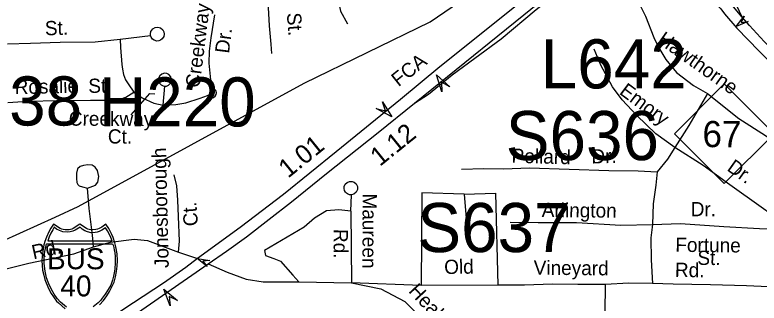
# Model space of a CAD drawing. Extents: x 1547597 to 1699558, y 810033 to 920809.
# Drawn here: x 1609660 to 1614635, y 849388 to 851314 of the extents above; entities that cross this region are included whole.
import ezdxf

# ---------------------------------------------------------------- set-up
doc = ezdxf.new("R2010")
doc.units = 0
for name, color, linetype in [('Exist Hydrographic Creek Single Shore', 7, 'Continuous'), ('Exist Road Non-System Type 51', 7, 'Continuous'), ('Exist Road Non-System Type 51 Label', 7, 'Continuous'), ('Exist Road Primary Interstate Divided Center Attributed', 7, 'Continuous'), ('Exist Road Primary Interstate Label', 7, 'Continuous'), ('Exist Road Primary Interstate Mileage Hundredths English Label', 7, 'Continuous'), ('Exist Road Primary Interstate Ramp 1 Lane Attributed', 7, 'Continuous'), ('Exist Road Primary Interstate Shield CELL', 7, 'Continuous'), ('Exist Road Primary Interstate Shield Number Label', 7, 'Continuous'), ('Exist Road Primary Interstate Structure Cantilever Sign Attributed CELL', 7, 'Continuous'), ('Exist Road Primary Interstate Structure Cantilever Sign Number Label', 7, 'Continuous'), ('Exist Road Primary Interstate Structure Ovrhead Sign Attributed CELL', 7, 'Continuous'), ('Exist Road Primary Interstate Structure Ovrhead Sign Number Label', 7, 'Continuous'), ('Exist Road Primary NC Divided Attributed', 7, 'Continuous'), ('Exist Road Primary NC Shield CELL', 7, 'Continuous'), ('Exist Road Primary NC Shield Number Label', 7, 'Continuous'), ('Exist Road Primary US Structure Non-Sys NCDOT Attributed CELL', 7, 'Continuous'), ('Exist Road Primary US Structure Non-Sys NCDOT Number Label', 7, 'Continuous')]:
    doc.layers.add(name, color=color, linetype=linetype)

msp = doc.modelspace()

# ---------------------------------------------------------------- linework, layer by layer
at = {"layer": 'Exist Hydrographic Creek Single Shore'}
for points in [[(1611594.1, 850857.9), (1612435.7, 851267.3), (1612822.7, 851531.9), (1613218.5, 851977.1), (1613319.3, 852016.9), (1613622.3, 852090.4), (1613757.8, 852160.1), (1613932.3, 852362.2), (1614064.9, 852556.6), (1614161.3, 852672.3), (1614372.7, 852674), (1614458.3, 852674), (1614584.2, 852789.9), (1615148.9, 852985.6), (1615306.6, 853204), (1615898.7, 853406.3), (1616283.8, 853510.1), (1617321.6, 853814.1), (1617885.8, 853975.5), (1618594.7, 854297), (1618697.7, 854345.4)], [(1609928.9, 849962.7), (1610082, 850033.2), (1611594.1, 850857.9)], [(1608890.7, 849280.9), (1609034.9, 849494.6), (1609101.1, 849537.2), (1609268.7, 849655.2), (1609454.2, 849749.5), (1609928.9, 849962.7)]]:
    msp.add_lwpolyline(points, dxfattribs=at)
at = {"layer": 'Exist Road Non-System Type 51'}
for p, q in [((1610363, 851151.8), (1610567.2, 851176.1)), ((1610650.6, 850710.7), (1610662.8, 850838.5))]:
    msp.add_line(p, q, dxfattribs=at)
for points in [[(1611803.9, 851681), (1611807.5, 851554.7), (1611811.1, 851457.3), (1611836.4, 851338.2), (1611883.2, 851255.3)], [(1611349.6, 851673.8), (1611342.3, 851536.7), (1611353.2, 851363.5), (1611360.4, 851240.8), (1611371.2, 851118.1), (1611374.8, 851056.8)], [(1613824.7, 851408.5), (1613874.8, 851305.7), (1613932.2, 851162.6), (1613964.8, 851094.1), (1614011.1, 851017.3), (1614083.7, 850930.2), (1614196.1, 850843.1), (1614289.6, 850789.6)], [(1610970.3, 850824.9), (1610969.5, 850880.7), (1610959.5, 850991), (1610961.3, 851071.4), (1610972.5, 851160.6), (1610995.5, 851314)], [(1610567.2, 851176.1), (1610565.9, 851188.7), (1610569.4, 851204.4), (1610581.9, 851220.4), (1610597.7, 851229.5), (1610614.6, 851231.7), (1610632.7, 851227.2), (1610648.1, 851214.2), (1610655.4, 851200.5), (1610657.9, 851185.4), (1610654.9, 851169.3), (1610645, 851153.7), (1610633.2, 851144.9), (1610622.1, 851140.5), (1610607.7, 851139.6), (1610591.2, 851144.4), (1610579.4, 851152.8), (1610570.6, 851165.4), (1610567.2, 851176.1)], [(1609611.2, 851121.6), (1609765.2, 851124.9), (1609963, 851131.3), (1610197, 851134.9), (1610363, 851151.8)], [(1610363, 851151.8), (1610366.1, 851095.7), (1610374.8, 850982.8), (1610378.8, 850950.7), (1610386.7, 850915.6), (1610399.8, 850881.1), (1610417.4, 850852.9), (1610454.3, 850798.3)], [(1614072.1, 850427.3), (1613944.1, 850519.2), (1613817.9, 850641.9), (1613720.5, 850746.5), (1613655.6, 850833.1), (1613576.3, 850977.4), (1613533, 851085.7)], [(1610662.8, 850838.5), (1610672.3, 850838.9), (1610687.2, 850844.6), (1610702.1, 850860.1), (1610707.1, 850880.7), (1610702.5, 850901.4), (1610689, 850916.4), (1610675.6, 850922.9), (1610660, 850924.8), (1610642.1, 850919), (1610629.4, 850907.4), (1610620.9, 850892.4), (1610620.5, 850874), (1610626.4, 850858.3), (1610638.6, 850846), (1610651.3, 850839.8), (1610662.8, 850838.5)], [(1609612.1, 850729.8), (1609746.1, 850737.5), (1609949.9, 850741.7), (1610165.7, 850743.8), (1610311.6, 850745), (1610364.1, 850751.7), (1610401.8, 850765.4), (1610454.3, 850798.3)], [(1610436.2, 850647.3), (1610561, 850789.4), (1610595.4, 850787.2)], [(1610454.3, 850798.3), (1610511.6, 850759.3), (1610588.9, 850724), (1610650.6, 850710.7)], [(1610947.5, 850775.3), (1610955.5, 850766.3), (1610965.4, 850761.5), (1610977.2, 850760.1), (1610988.3, 850762.7), (1610999, 850770.9), (1611005.7, 850782.1), (1611007.9, 850794.5), (1611003, 850809.2), (1610992.4, 850820.2), (1610979.9, 850825.1), (1610970.3, 850824.9)], [(1610947.5, 850775.3), (1610971.2, 850789.6), (1610970.3, 850824.9)], [(1614289.6, 850789.6), (1614213.4, 850655.3), (1614166.4, 850576.1), (1614072.1, 850427.3)], [(1614289.6, 850789.6), (1614499.9, 850622.6), (1614679.1, 850508.9), (1614923.7, 850344.4), (1615083.8, 850219.7)], [(1610650.6, 850710.7), (1610736.6, 850715.2), (1610802.6, 850726), (1610899.1, 850758.1), (1610947.5, 850775.3)], [(1614072.1, 850427.3), (1614022.9, 850349.3), (1613953.4, 850264.5)], [(1614855.5, 849882.8), (1614648.3, 850030.5), (1614439.2, 850178.2), (1614260.7, 850307.5), (1614072.1, 850427.3)], [(1610144.7, 850155.6), (1610199.2, 850177.4), (1610213.6, 850197.1), (1610220.2, 850235), (1610213, 850275.1), (1610197.4, 850297.3), (1610175.7, 850309.7), (1610147.7, 850312.3), (1610117.6, 850308.7), (1610095.6, 850301.1), (1610079.3, 850285.4), (1610070.7, 850255.6), (1610072.2, 850221.8), (1610074.1, 850194.3), (1610080.6, 850180), (1610089.6, 850171.4), (1610111.1, 850164.9), (1610144.7, 850155.6)], [(1612645.3, 850284.4), (1612795.2, 850287.6), (1612926.8, 850285.3), (1613100.8, 850293.2), (1613365.5, 850282.3), (1613630, 850274.4), (1613827.7, 850272.8), (1613953.4, 850264.5)], [(1610754.6, 849727.8), (1610760.1, 849803.4), (1610754.6, 849967.5), (1610749.1, 850076.3), (1610741.8, 850171.8), (1610723.9, 850244.9)], [(1613953.4, 850264.5), (1613945.8, 850176.8), (1613927.4, 850051.1), (1613923, 849913.3)], [(1611883.6, 850117.8), (1611876.2, 850122.3), (1611869.2, 850130.3), (1611863.6, 850140.6), (1611860.3, 850154.1), (1611861.4, 850168.4), (1611867.4, 850182.1), (1611881.1, 850195.3), (1611895.9, 850201.6), (1611914.1, 850201.6), (1611928.4, 850196.1), (1611940.4, 850185.9), (1611950, 850167.4), (1611949.4, 850146.7), (1611941.8, 850129.2), (1611925.7, 850116.3), (1611910.8, 850111.8), (1611897.7, 850112.9), (1611883.6, 850117.8)], [(1610184.9, 849765.3), (1610177.9, 849842.1), (1610155.7, 850021), (1610144.7, 850155.6)], [(1611904.8, 850003.2), (1611910.8, 850111.8)], [(1612380.1, 850126.2), (1612376.5, 849505.5)], [(1612663, 850115.3), (1612380.1, 850126.2)], [(1612663, 850115.3), (1612873.3, 850122.6)], [(1612663, 850115.3), (1612681.1, 849901.2)], [(1612873.3, 850122.6), (1612888.7, 849508.1)], [(1611904.8, 850003.2), (1611824.5, 850011.3), (1611742.1, 850005.3), (1611663.8, 849957), (1611593.4, 849896.7), (1611328.3, 849739.9)], [(1611904.8, 850003.2), (1611909.7, 849523)], [(1612970.2, 849930.2), (1613157.8, 849926.9), (1613413.5, 849926.1), (1613711, 849909.2), (1613923, 849913.3)], [(1613923, 849913.3), (1613911.4, 849823.5), (1613912.6, 849677.6), (1613921.6, 849519.5)], [(1613923, 849913.3), (1614108.9, 849919.9), (1614398.5, 849901), (1614637.9, 849886.4), (1614855.5, 849882.8)], [(1610184.9, 849765.3), (1610299.7, 849795), (1610457, 849816.3), (1610546.3, 849807.8), (1610754.6, 849727.8)], [(1608516.1, 849735.5), (1608958.3, 849658.9), (1609302.8, 849590.8), (1609528.1, 849599.3), (1609753.5, 849654.7), (1610053.1, 849718.4), (1610184.9, 849765.3)], [(1611328.3, 849739.9), (1611334.3, 849705.7), (1611390.6, 849685.6), (1611434.7, 849669.5), (1611517.1, 849575), (1611558.4, 849531.2)], [(1610754.6, 849727.8), (1610880.9, 849686.6)], [(1610951.8, 849650.5), (1611077.9, 849595), (1611205.5, 849548.2), (1611320.3, 849531.2), (1611558.4, 849531.2)], [(1611558.4, 849531.2), (1611909.7, 849523)], [(1611909.7, 849523), (1612105.3, 849484.7), (1612266.9, 849399.5), (1612424.2, 849242.1), (1612589.7, 849074.1)], [(1612376.5, 849505.5), (1611909.7, 849523)], [(1612888.7, 849508.1), (1612376.5, 849505.5)], [(1613607.9, 849513.1), (1613423.5, 849512.8), (1613253.4, 849514.7), (1613066.1, 849508.1), (1612888.7, 849508.1)], [(1613616.3, 848999.2), (1613606.9, 849135.3), (1613606.3, 849323.2), (1613607.9, 849513.1)], [(1613921.6, 849519.5), (1613761.8, 849522.4), (1613607.9, 849513.1)], [(1615139.8, 849441.5), (1615073.2, 849463.1), (1615051.3, 849474.8), (1614934, 849486.3), (1614796.8, 849491.6), (1614550.7, 849503.9), (1614311.1, 849510.4), (1614061.4, 849514.9), (1613921.6, 849519.5)]]:
    msp.add_lwpolyline(points, dxfattribs=at)
at = {"layer": 'Exist Road Primary Interstate Divided Center Attributed'}
for points in [[(1612330.6, 850725.5), (1613224.7, 851447.9), (1613346.8, 851542.9), (1613591.4, 851734.7), (1613886.3, 851991.7)], [(1613010.2, 851375.8), (1612501.3, 850967.3), (1612238.6, 850748.3), (1611807.5, 850398.9), (1611455.2, 850113.6), (1611165.3, 849893.8), (1610880.9, 849686.6)], [(1609818, 848863.7), (1610951.8, 849650.5), (1611075.2, 849735.8), (1611208.1, 849832), (1611360.5, 849948.2), (1611508.2, 850064.4), (1611742.4, 850253.5), (1612088.1, 850529.5), (1612330.6, 850725.5)], [(1610880.9, 849686.6), (1610801.9, 849625.3), (1610654, 849520.7), (1610451.7, 849389.8), (1610101.9, 849158.9), (1609835, 848982.1), (1609597.4, 848825.8)]]:
    msp.add_lwpolyline(points, dxfattribs=at)
at = {"layer": 'Exist Road Primary Interstate Ramp 1 Lane Attributed'}
for points in [[(1614522.4, 851299.9), (1614466.2, 851418.6), (1614445.7, 851474.8), (1614436.9, 851512), (1614425.3, 851584.9), (1614423, 851653.9), (1614424.4, 851686.9), (1614426.7, 851723.6), (1614431, 851830.6), (1614433.4, 851880.4), (1614440.5, 851930.2), (1614442.8, 851987.1), (1614447.6, 852041.6), (1614457, 852164.8), (1614461.8, 852233.6), (1614473.6, 852290.4), (1614483.1, 852328.4), (1614492.6, 852356.8), (1614511.5, 852387.6), (1614530.5, 852413.7), (1614558.9, 852449.2), (1614594.4, 852484.8), (1614690.2, 852571.5)], [(1612330.6, 850725.5), (1612424.5, 850784.1), (1612582.5, 850913.7), (1612735.8, 851026.2), (1612911.5, 851155.4), (1613143.8, 851351), (1613297.1, 851470.7), (1613360.4, 851491.1), (1613412.5, 851502.3), (1613451.5, 851507.9), (1613498, 851511.6), (1613617.8, 851514.9), (1613713.9, 851519.1), (1613851.6, 851526.5), (1614000.4, 851532.1), (1614091.6, 851530.2), (1614139.9, 851526.5), (1614179, 851515.3), (1614214.4, 851500.4), (1614242.3, 851481.8), (1614272, 851459.5), (1614311.1, 851424.1), (1614379.4, 851353.8)]]:
    msp.add_lwpolyline(points, dxfattribs=at)
at = {"layer": 'Exist Road Primary Interstate Shield CELL'}
for points in [[(1610225.7, 849377.4), (1610251.7, 849404.8), (1610274.7, 849435.9), (1610293, 849464.9), (1610309, 849498), (1610322.5, 849529), (1610333.1, 849564.3), (1610340.2, 849598.5), (1610343.8, 849634.2), (1610346.2, 849673.8), (1610343.5, 849718.3), (1610335.7, 849763.9), (1610328.5, 849792.2), (1610317.4, 849826.2), (1610308.4, 849847.9), (1610287.6, 849886.3), (1610268.8, 849915.9), (1610241.6, 849896.7), (1610223.8, 849887.3), (1610213, 849882.4), (1610201.9, 849880.2), (1610181.4, 849877.8), (1610168.5, 849878.3), (1610156.5, 849881), (1610146.4, 849883.2), (1610138.2, 849887.3), (1610093.9, 849915.9), (1610049.6, 849887.3), (1610040.4, 849883), (1610030.9, 849881), (1610021.7, 849878.5), (1610006.6, 849877.8), (1609995, 849878.1), (1609983.1, 849880.2), (1609973.8, 849882.2), (1609963.2, 849887.3), (1609918.1, 849915.9), (1609900.4, 849890.2), (1609885.9, 849864.8), (1609870.6, 849828.8), (1609861, 849801), (1609854.2, 849778.1), (1609845.9, 849736.2), (1609841.6, 849699.6), (1609840.8, 849673.8), (1609845.5, 849609.3), (1609852.6, 849574.9), (1609859.8, 849547.1), (1609883.7, 849487.1), (1609901.6, 849453.5), (1609917, 849429.3), (1609938.6, 849402.1), (1609950.3, 849389.2), (1609995.1, 849350)], [(1610003.9, 849361.3), (1609964.1, 849393.9), (1609942.7, 849419), (1609922.6, 849448.4), (1609904.8, 849478.5), (1609885.7, 849518.2), (1609872.2, 849558.1), (1609862.4, 849601.1), (1609855.8, 849653.8), (1609855.1, 849685.8), (1609857.1, 849716.7), (1609860, 849732.8), (1609863.9, 849752.9), (1609871.8, 849783.9), (1610313.4, 849784.1), (1610318.1, 849771.9), (1610324.4, 849744.9), (1610327.8, 849724), (1610331.2, 849700), (1610330, 849658.9), (1610328, 849616.3), (1610324.1, 849591.1), (1610318.9, 849568.2), (1610311.7, 849542.7), (1610300.2, 849508.9), (1610284.3, 849480.2), (1610264.4, 849448.4), (1610242.9, 849420.5), (1610233.6, 849409), (1610215.9, 849390.3), (1610183.6, 849364.4)]]:
    msp.add_lwpolyline(points, dxfattribs=at)
msp.add_lwpolyline([(1609923.5, 849895.1), (1609912.5, 849878.2), (1609899.8, 849855.4), (1609889.7, 849831.7), (1609879.3, 849805.5), (1610310.9, 849805.4), (1610300.8, 849827.8), (1610290.1, 849850.3), (1610278.8, 849870.9), (1610265.1, 849890.8), (1610240.9, 849875.6), (1610223.3, 849867.2), (1610209.1, 849862.3), (1610197.1, 849859.6), (1610178.5, 849858.2), (1610170.2, 849858.7), (1610144.3, 849864.5), (1610126.7, 849871.7), (1610110, 849882.9), (1610096.5, 849895.6), (1610062.3, 849874.9), (1610047.2, 849868.2), (1610029.7, 849863.8), (1610010.6, 849861.4), (1609981.2, 849864.6), (1609958.1, 849872.5), (1609938.2, 849882.9)], close=True, dxfattribs=at)
at = {"layer": 'Exist Road Primary Interstate Structure Cantilever Sign Attributed CELL'}
msp.add_lwpolyline([(1610697.9, 849369.4), (1610655.1, 849481), (1610747.9, 849405.8), (1610690.2, 849432.7)], close=True, dxfattribs=at)
at = {"layer": 'Exist Road Primary Interstate Structure Ovrhead Sign Attributed CELL'}
for points in [[(1614562.4, 851269.8), (1614480.9, 851237.1), (1614535.1, 851306.2), (1614516.1, 851263.4)], [(1612514.7, 850800.3), (1612479.1, 850914.3), (1612566.9, 850833.4), (1612511, 850863.9)], [(1612117.6, 850734), (1612180.6, 850632.4), (1612075.3, 850688.9), (1612137, 850673.3)]]:
    msp.add_lwpolyline(points, close=True, dxfattribs=at)
at = {"layer": 'Exist Road Primary NC Divided Attributed'}
for points in [[(1614522.4, 851299.9), (1614328.2, 851533.8), (1614227.4, 851655.3), (1614134.4, 851765.4), (1613936.5, 852028)], [(1614379.4, 851353.8), (1614403.8, 851321.2), (1614487, 851224.7), (1614635.3, 851071), (1614786.3, 850921.2), (1614859.9, 850845.4)], [(1614916, 850884), (1614835.6, 850964.6), (1614669.2, 851135.6), (1614571.7, 851243.6), (1614522.4, 851299.9)]]:
    msp.add_lwpolyline(points, dxfattribs=at)
at = {"layer": 'Exist Road Primary NC Shield CELL'}
msp.add_lwpolyline([(1614069.6, 850520.1), (1614402.6, 850853.1), (1614735.6, 850520.1), (1614402.6, 850187.1)], close=True, dxfattribs=at)
at = {"layer": 'Exist Road Primary US Structure Non-Sys NCDOT Attributed CELL'}
msp.add_lwpolyline([(1610944.6, 849632), (1610878.1, 849685.5), (1610962.4, 849672.5), (1610917.1, 849668.3)], close=True, dxfattribs=at)

# ---------------------------------------------------------------- texts
at = {"layer": 'Exist Road Non-System Type 51 Label'}
for s, rotation, p in [('Creekway', 82.8364, (1610893.9, 850823.9)), ('St.', 274.4465, (1611477.6, 851325.7)), ('St.', 1.8503, (1609861.9, 851177.3)), ('Dr.', 82.8364, (1611091, 851053.5)), ('Hawthorne', 324.7862, (1613949.5, 851131.7)), ('Rosalie', 1.1998, (1609659.1, 850784.9)), ('St.', 0.4883, (1610151, 850792.8)), ('Emory', 323.1796, (1613695.1, 850789.9)), ('Creekway', 359.6956, (1610020.1, 850574.2)), ('Ct.', 359.3518, (1610280.8, 850455.3)), ('Jonesborough', 91.3367, (1610688.9, 849623.4)), ('Pollard', 358.5216, (1612979.5, 850326.3)), ('Dr.', 1.3994, (1613515.2, 850320.9)), ('Dr.', 324.7622, (1614414.8, 850278.4)), ('Maureen', 269.7936, (1611984.8, 850121.1)), ('Ct.', 94.3519, (1610884.5, 849905.7)), ('Arlington', 359.3776, (1613181.7, 849964.2)), ('Dr.', 359.9199, (1614178, 849969.1)), ('Rd.', 269.7936, (1611791.4, 849884.1)), ('Rd.', 12.4134, (1609784, 849680.6)), ('Fortune', 359.3776, (1614074.6, 849731.3)), ('St.', 359.3776, (1614222.3, 849644)), ('Old', 0.8599, (1612530.5, 849582.6)), ('Vineyard', 359.4445, (1613127.8, 849578.4)), ('Rd.', 358.9753, (1614071.8, 849563.9)), ('Healy', 312.9895, (1612286.5, 849465.2))]:
    msp.add_text(s, height=95, rotation=rotation, dxfattribs=at).set_placement(p)
at = {"layer": 'Exist Road Primary Interstate Label'}
msp.add_text('FCA', height=95, rotation=38.7269, dxfattribs=at).set_placement((1612224.4, 850830.6))
at = {"layer": 'Exist Road Primary Interstate Mileage Hundredths English Label'}
for s, rotation, p in [('1.12', 38.9531, (1612099.7, 850297.7)), ('1.01', 39.0084, (1611486.2, 850219.1))]:
    msp.add_text(s, height=125, rotation=rotation, dxfattribs=at).set_placement(p)
at = {"layer": 'Exist Road Primary Interstate Shield Number Label'}
for s, p in [('BUS', (1609874.5, 849614.7)), ('40', (1609963.9, 849433.3))]:
    msp.add_text(s, height=140, dxfattribs=at).set_placement(p)
at = {"layer": 'Exist Road Primary Interstate Structure Cantilever Sign Number Label'}
for s, p in [('L642', (1613175.4, 850823)), ('L638', (1609133.3, 850575.2))]:
    msp.add_text(s, height=328.08, dxfattribs=at).set_placement(p)
at = {"layer": 'Exist Road Primary Interstate Structure Ovrhead Sign Number Label'}
for s, p in [('S636', (1612941.4, 850343.9)), ('S637', (1612350.4, 849729.4))]:
    msp.add_text(s, height=328.08, dxfattribs=at).set_placement(p)
at = {"layer": 'Exist Road Primary NC Shield Number Label'}
msp.add_text('67', height=175, dxfattribs=at).set_placement((1614256.8, 850430.4))
at = {"layer": 'Exist Road Primary US Structure Non-Sys NCDOT Number Label'}
msp.add_text('H220', height=328.08, dxfattribs=at).set_placement((1610221, 850568.7))

doc.saveas('drawing.dxf')
